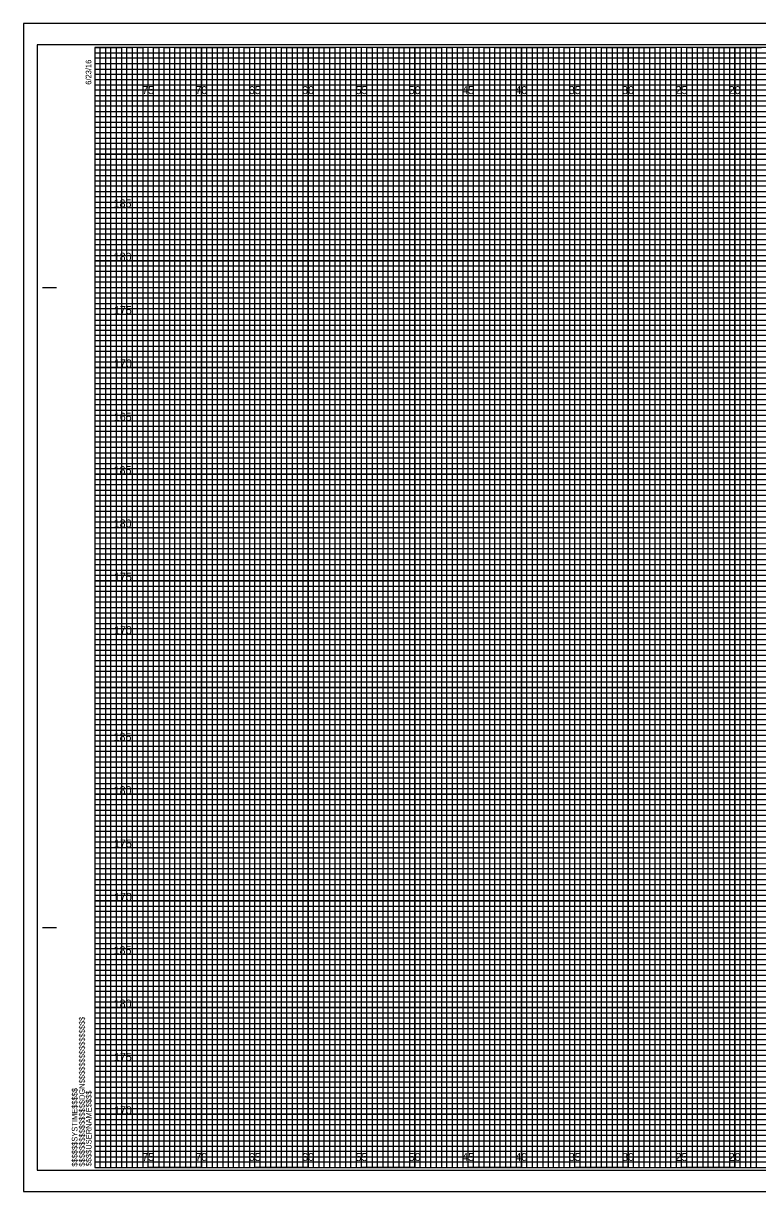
# Model space of a CAD drawing. Extents: x -7 to 162, y -2 to 767.
# Drawn here: x -6.7 to 62.1, y 107.8 to 217.2 of the extents above; entities that cross this region are included whole.
import ezdxf

# ---------------------------------------------------------------- set-up
doc = ezdxf.new("R2010")
doc.units = 0
for name, color, linetype in [('Exist Cross Section Cell', 7, 'Continuous'), ('Prop CMT Pvmt Course 1', 7, 'Continuous'), ('Prop CMT Pvmt Course 1 Wedge', 7, 'Continuous'), ('Prop CMT Pvmt Course 2', 7, 'Continuous'), ('Prop CMT Pvmt Course 3', 7, 'Continuous'), ('Prop CMT Pvmt Surface Shoulder', 7, 'Continuous'), ('Prop CMT Shld Paved Course 2', 7, 'Continuous'), ('Prop CMT Shld Paved Course 3', 7, 'Continuous'), ('Prop CMT Slope Grass', 7, 'Continuous'), ('Prop CMT Subgrade Earthwork', 7, 'Continuous'), ('Scratch_Level_0', 7, 'Continuous')]:
    doc.layers.add(name, color=color, linetype=linetype)

msp = doc.modelspace()

# ---------------------------------------------------------------- linework, layer by layer
at = {"layer": 'Prop CMT Pvmt Course 1'}
for p, q in [((0, 214.5), (130, 214.5)), ((130, 213.99), (0, 213.99)), ((0, 213.99), (0, 213.5)), ((0, 213.5), (130, 213.5)), ((130, 212.94), (0, 212.94)), ((0, 212.94), (0, 212)), ((0, 212), (160, 212))]:
    msp.add_line(p, q, dxfattribs=at)
for points in [[(0, 211.5), (135, 211.5), (160, 211.5), (160, 211), (0, 211)], [(0, 210.5), (160, 210.5), (160, 209.5), (0, 209.5)], [(0, 209), (160, 209), (160, 208.5), (0, 208.49)], [(0, 208), (160, 208), (160, 207), (0, 207)], [(0, 206.5), (160, 206.5), (160, 206), (0, 206)], [(0, 205.5), (160, 205.5), (160, 204.5), (0, 204.5)], [(0, 204), (160, 204), (160, 203.5), (0, 203.5)], [(0, 203), (160, 203), (160, 202), (0, 202)], [(0, 201.5), (160, 201.5), (160, 201), (0, 201)], [(0, 200.5), (160, 200.5), (160, 199.5), (0, 199.5)], [(0, 199), (160, 199), (160, 198.5), (0, 198.5)], [(0, 198), (160, 198), (160, 196.97), (160, 196.5), (160, 196), (0, 196)], [(0, 197), (160, 197), (160, 196.5), (0, 196.5)], [(0, 195.5), (160, 195.5), (160, 194.5), (0, 194.52)], [(0, 194.52), (160, 194.5), (160, 194), (0, 194)], [(0, 193.5), (160, 193.5), (160, 193), (0, 193)], [(0, 192), (160, 192), (160, 191.5), (0, 191.5)], [(0, 191), (160, 191), (160, 190.5), (0, 190.5)], [(-0.04, 189.44), (160, 189.44), (160, 188.94), (-0.04, 188.94)], [(0, 188.5), (160, 188.5), (160, 188), (0, 188)], [(0, 187), (160, 187), (160, 186.5), (0, 186.5)], [(0, 186), (160, 186), (160, 185.5), (0, 185.5)], [(0, 184.5), (160, 184.5), (160, 184), (0, 184)], [(0, 183.5), (160, 183.5), (160, 183), (0, 183)], [(0, 182), (160, 182), (160, 181.5), (0, 181.5)], [(0, 181), (160, 181), (160, 180.5), (0, 180.5)], [(0, 179.5), (160, 179.5), (160, 178.99), (0, 179)], [(0, 178.5), (160, 178.5), (160, 178), (0, 178)], [(0, 177), (160, 177), (160, 176.5), (0, 176.5)], [(0, 176), (160, 176), (160, 175.5), (0, 175.5)], [(0, 174.5), (160, 174.5), (160, 174), (0, 174)], [(0, 173.5), (160, 173.5), (160, 173), (0, 173)], [(0, 172), (160, 172), (160, 171.5), (0, 171.5)], [(0, 171), (160, 171), (160, 170.5), (0, 170.5)], [(0, 169.5), (160, 169.5), (160, 169), (0, 169)], [(0, 168.5), (160.03, 168.46), (160, 168), (0, 168)], [(0, 167), (160, 167), (160, 166.5), (0, 166.5)], [(0, 166), (160, 166), (160, 165.5), (0, 165.5)], [(0, 164.5), (160, 164.5), (160, 164), (0, 164)], [(0, 163.5), (160, 163.5), (160, 163), (0, 163)], [(0, 162), (160, 162), (160, 161.5), (0, 161.5)], [(0, 161), (160, 161), (160, 160.5), (0, 160.5)], [(0, 159.5), (160, 159.5), (160, 159), (0, 159)], [(0, 158.5), (160, 158.5), (160, 158), (0, 158)], [(0, 157), (160, 157), (160, 156.5), (0, 156.5)], [(0, 156), (160, 156), (160, 155.5), (0, 155.5)], [(0, 154.5), (160, 154.5), (160, 154), (0, 154)], [(0, 153.5), (160, 153.5), (160, 153), (0, 153)], [(0, 152), (160, 152), (160, 151.5), (0, 151.5)], [(0, 151), (160, 151), (160, 150.5), (0, 150.5)], [(0, 149.5), (160, 149.5), (160, 148.99), (0, 149)], [(0, 148.5), (160, 148.5), (160, 148), (0, 148)], [(0, 147), (160, 147), (160, 146.5), (0, 146.5)], [(0, 146), (160, 146), (160, 145.5), (0, 145.5)], [(0, 144.5), (160, 144.5), (160, 144), (0, 144)], [(0, 143.5), (160, 143.5), (160, 143), (0, 143)], [(0, 142), (160, 142), (160, 141.5), (0, 141.5)], [(0, 141), (160, 141), (160, 140.5), (0, 140.5)], [(0, 139.5), (160, 139.5), (160, 139), (0, 139)], [(0, 138.5), (160.03, 138.46), (160, 138), (0, 138)], [(0, 137), (160, 137), (160, 136.5), (0, 136.5)], [(0, 136), (160, 136), (160, 135.5), (0, 135.5)], [(0, 134.5), (160, 134.5), (160, 134), (0, 134)], [(0, 133.5), (160, 133.5), (160, 133), (0, 133)], [(0, 132), (160, 132), (160, 131.5), (0, 131.5)], [(0, 131), (160, 131), (160, 130.5), (0, 130.5)], [(0, 129.5), (160, 129.5), (160, 129), (0, 129)], [(0, 128.5), (160, 128.5), (160, 128), (0, 128)], [(0, 127), (160, 127), (160, 126.5), (0, 126.5)], [(0, 126), (160, 126), (160, 125.5), (0, 125.5)], [(0, 124.5), (160, 124.5), (160, 124), (0, 124)], [(0, 123.5), (160, 123.5), (160, 123), (0, 123)], [(0, 122), (160, 122), (160, 121.5), (0, 121.5)], [(0, 121), (160, 121), (160, 120.5), (0, 120.5)], [(0, 119.5), (160, 119.5), (160, 119), (0, 119)], [(0, 118.5), (160, 118.5), (160, 118), (0, 118)], [(0, 117), (160, 117), (160, 116.5), (0, 116.5)], [(0, 116), (160, 116), (160, 115.5), (0, 115.5)], [(0, 114.5), (160, 114.5), (160, 114), (0, 114)], [(0, 113.5), (160, 113.5), (160, 113), (0, 113)], [(0, 112), (160, 112), (160, 111.5), (0, 111.5)], [(0, 111), (160, 111), (160, 110.5), (0, 110.5)]]:
    msp.add_lwpolyline(points, dxfattribs=at)
at = {"layer": 'Prop CMT Pvmt Course 2'}
for p, q in [((5, 110), (5, 215)), ((10, 110), (10, 215)), ((15, 110), (15, 215)), ((20, 110), (20, 215)), ((25, 110), (25, 215)), ((30, 110), (30, 215)), ((35, 110), (35, 215)), ((40, 110), (40, 215)), ((45, 110), (45, 215)), ((50, 110), (50, 215)), ((55, 110), (55, 215)), ((60, 110), (60, 215)), ((0, 210), (160, 210)), ((0, 205), (160, 205)), ((0, 200), (160, 200)), ((0, 195), (160, 195)), ((0, 190), (160, 190)), ((0, 185), (160, 185)), ((0, 180), (160, 180)), ((0, 175), (160, 175)), ((0, 170), (160, 170)), ((0, 165), (160, 165)), ((0, 160), (160, 160)), ((0, 155), (160, 155)), ((0, 150), (160, 150)), ((0, 145), (160, 145)), ((0, 140), (160, 140)), ((0, 135), (160, 135)), ((0, 130), (160, 130)), ((0, 125), (160, 125)), ((0, 120), (160, 120)), ((0, 115), (160, 115))]:
    msp.add_line(p, q, dxfattribs=at)
at = {"layer": 'Prop CMT Pvmt Course 3'}
for p, q in [((161.65, 217.25), (-6.7, 217.25)), ((-6.7, 217.25), (-6.7, 107.75)), ((-6.7, 107.75), (161.65, 107.75))]:
    msp.add_line(p, q, dxfattribs=at)
at = {"layer": 'Prop CMT Pvmt Surface Shoulder'}
for points in [[(0, 215), (2.5, 215), (2.5, 110), (7.5, 110), (7.5, 215), (12.5, 215), (12.5, 110), (17.5, 110), (17.5, 215), (22.5, 215), (22.5, 110), (27.5, 110), (27.5, 215), (32.5, 215), (32.5, 110), (37.5, 110), (37.5, 215), (42.5, 215), (42.5, 110), (47.5, 110), (47.5, 215), (52.5, 215), (52.5, 110), (57.5, 110), (57.5, 215), (62.5, 215)], [(0, 212.5), (137.5, 212.5)], [(0, 202.5), (160, 202.5), (160, 207.5), (0, 207.5)], [(0, 192.5), (160, 192.5), (160, 197.5), (0, 197.5)], [(0, 182.5), (160, 182.5), (160, 187.5), (0, 187.5)], [(0, 172.5), (160, 172.5), (160, 177.5), (0, 177.5)], [(0, 162.5), (160, 162.5), (160, 167.5), (0, 167.5)], [(0, 152.5), (160, 152.5), (160, 157.5), (0, 157.5)], [(0, 142.5), (160, 142.5), (160, 147.5), (0, 147.5)], [(0, 132.5), (160, 132.5), (160, 137.5), (0, 137.5)], [(0, 122.5), (160, 122.5), (160, 127.5), (0, 127.5)], [(0, 112.5), (160, 112.5), (160, 117.5), (0, 117.5)]]:
    msp.add_lwpolyline(points, dxfattribs=at)
at = {"layer": 'Prop CMT Shld Paved Course 2'}
msp.add_lwpolyline([(-6.7, 107.75), (161.65, 107.75), (161.65, 217.25), (-6.7, 217.25)], close=True, dxfattribs=at)
at = {"layer": 'Prop CMT Shld Paved Course 3'}
msp.add_lwpolyline([(-5.4, 109.75), (161.2, 109.75), (161.2, 215.25), (-5.4, 215.25)], close=True, dxfattribs=at)
at = {"layer": 'Prop CMT Slope Grass'}
for points in [[(0, 110), (0.5, 110), (0.5, 215), (1, 215), (1, 110)], [(1, 110), (1.5, 110), (1.5, 215), (2, 215), (2, 110)], [(2.5, 110), (3, 110), (3, 215), (3.5, 215), (3.5, 110)], [(3.5, 110), (4, 110), (4, 215), (4.5, 215), (4.5, 110)], [(5, 110), (5.5, 110), (5.5, 215), (6, 215), (6, 110)], [(6, 110), (6.5, 110), (6.5, 215), (7, 215), (7, 110)], [(7.5, 110), (8, 110), (8, 215), (8.5, 215), (8.5, 110)], [(8.5, 110), (9, 110), (9, 215), (9.5, 215), (9.5, 110)], [(10, 110), (10.5, 110), (10.5, 215), (11, 215), (11, 110)], [(11, 110), (11.5, 110), (11.5, 215), (12, 215), (12, 110)], [(12.5, 110), (13, 110), (13, 215), (13.5, 215), (13.5, 110)], [(13.5, 110), (14, 110), (14, 215), (14.5, 215), (14.5, 110)], [(15, 110), (15.5, 110), (15.5, 215), (16, 215), (16, 110)], [(16, 110), (16.5, 110), (16.5, 215), (17, 215), (17, 110)], [(17.5, 110), (18, 110), (18, 215), (18.5, 215), (18.5, 110)], [(18.5, 110), (19, 110), (19, 215), (19.5, 215), (19.5, 110)], [(20, 110), (20.5, 110), (20.5, 215), (21, 215), (21, 110)], [(21, 110), (21.5, 110), (21.5, 215), (22, 215), (22, 110)], [(22.5, 110), (23, 110), (23, 215), (23.5, 215), (23.5, 110)], [(23.5, 110), (24, 110), (24, 215), (24.5, 215), (24.5, 110)], [(25, 110), (25.5, 110), (25.5, 215), (26, 215), (26, 110)], [(26, 110), (26.5, 110), (26.5, 215), (27, 215), (27, 110)], [(27.5, 110), (28, 110), (28, 215), (28.5, 215), (28.5, 110)], [(28.5, 110), (29, 110), (29, 215), (29.5, 215), (29.5, 110)], [(30, 110), (30.5, 110), (30.5, 215), (31, 215), (31, 110)], [(31, 110), (31.5, 110), (31.5, 215), (32, 215), (32, 110)], [(32.5, 110), (33, 110), (33, 215), (33.5, 215), (33.5, 110)], [(33.5, 110), (34, 110), (34, 215), (34.5, 215), (34.5, 110)], [(35, 110), (35.5, 110), (35.5, 215), (36, 215), (36, 110)], [(36, 110), (36.5, 110), (36.5, 215), (37, 215), (37, 110)], [(37.5, 110), (38, 110), (38, 215), (38.5, 215), (38.5, 110)], [(38.5, 110), (39, 110), (39, 215), (39.5, 215), (39.5, 110)], [(40, 110), (40.5, 110), (40.5, 215), (41, 215), (41, 110)], [(41, 110), (41.5, 110), (41.5, 215), (42, 215), (42, 110)], [(42.5, 110), (43, 110), (43, 215), (43.5, 215), (43.5, 110)], [(43.5, 110), (44, 110), (44, 215), (44.5, 215), (44.5, 110)], [(45, 110), (45.5, 110), (45.5, 215), (46, 215), (46, 110)], [(46, 110), (46.5, 110), (46.5, 215), (47, 215), (47, 110)], [(47.5, 110), (48, 110), (48, 215), (48.5, 215), (48.5, 110)], [(48.5, 110), (49, 110), (49, 215), (49.5, 215), (49.5, 110)], [(50, 110), (50.5, 110), (50.5, 215), (51, 215), (51, 110)], [(51, 110), (51.5, 110), (51.5, 215), (52, 215), (52, 110)], [(52.5, 110), (53, 110), (53, 215), (53.5, 215), (53.5, 110)], [(53.5, 110), (54, 110), (54, 215), (54.5, 215), (54.5, 110)], [(55, 110), (55.5, 110), (55.5, 215), (56, 215), (56, 110)], [(56, 110), (56.5, 110), (56.5, 215), (57, 215), (57, 110)], [(57.5, 110), (58, 110), (58, 215), (58.5, 215), (58.5, 110)], [(58.5, 110), (59, 110), (59, 215), (59.5, 215), (59.5, 110)], [(60, 110), (60.5, 110), (60.5, 215), (61, 215), (61, 110)], [(61, 110), (61.5, 110), (61.5, 215), (62, 215), (62, 110)]]:
    msp.add_lwpolyline(points, dxfattribs=at)
at = {"layer": 'Prop CMT Subgrade Earthwork'}
for p, q in [((-4.9, 192.5), (-3.65, 192.5)), ((-4.85, 192.5), (-3.6, 192.5)), ((-4.9, 132.5), (-3.65, 132.5)), ((-4.85, 132.5), (-3.6, 132.5)), ((0, 110), (0, 110)), ((0, 110), (0, 110)), ((0, 110), (0, 110)), ((0, 110), (0, 110)), ((0, 110), (0, 110)), ((0, 110), (0, 110)), ((0, 110), (0, 110))]:
    msp.add_line(p, q, dxfattribs=at)
msp.add_lwpolyline([(160, 215), (0, 215), (0, 110), (160, 110)], close=True, dxfattribs=at)
at = {"layer": 'Scratch_Level_0'}
for p, q in [((5, 215), (0, 215)), ((5, 110), (5, 215)), ((15, 215), (10, 215)), ((10, 215), (10, 110)), ((15, 110), (15, 215)), ((25, 215), (20, 215)), ((20, 215), (20, 110)), ((25, 110), (25, 215)), ((35, 215), (30, 215)), ((30, 215), (30, 110)), ((35, 110), (35, 215)), ((45, 215), (40, 215)), ((40, 215), (40, 110)), ((45, 110), (45, 215)), ((55, 215), (50, 215)), ((50, 215), (50, 110)), ((55, 110), (55, 215)), ((65, 215), (60, 215)), ((60, 215), (60, 110)), ((10, 110), (5, 110)), ((20, 110), (15, 110)), ((30, 110), (25, 110)), ((40, 110), (35, 110)), ((50, 110), (45, 110)), ((60, 110), (55, 110))]:
    msp.add_line(p, q, dxfattribs=at)
for points in [[(0, 210), (160, 210), (160, 205), (0, 205)], [(0, 200), (160, 200), (160, 195), (0, 195)], [(0, 190), (160, 190), (160, 185), (0, 185)], [(0, 180), (160, 180), (160, 175), (0, 175)], [(0, 170), (160, 170), (160, 165), (0, 165)], [(0, 160), (160, 160), (160, 155), (0, 155)], [(0, 150), (160, 150), (160, 145), (0, 145)], [(0, 140), (160, 140), (160, 135), (0, 135)], [(0, 130), (160, 130), (160, 125), (0, 125)], [(0, 120), (160, 120), (160, 115), (0, 115)]]:
    msp.add_lwpolyline(points, dxfattribs=at)

# ---------------------------------------------------------------- texts
at = {"layer": 'Exist Cross Section Cell'}
for s, p in [('75', (4.44, 210.62)), ('70', (9.43, 210.62)), ('65', (14.44, 210.62)), ('60', (19.43, 210.62)), ('55', (24.44, 210.62)), ('50', (29.43, 210.62)), ('45', (34.44, 210.62)), ('40', (39.43, 210.62)), ('35', (44.44, 210.62)), ('30', (49.43, 210.62)), ('25', (54.44, 210.62)), ('20', (59.43, 210.62)), ('75', (4.44, 110.62)), ('70', (9.43, 110.62)), ('65', (14.44, 110.62)), ('60', (19.43, 110.62)), ('55', (24.44, 110.62)), ('50', (29.43, 110.62)), ('45', (34.44, 110.62)), ('40', (39.43, 110.62)), ('35', (44.44, 110.62)), ('30', (49.43, 110.62)), ('25', (54.44, 110.62)), ('20', (59.43, 110.62))]:
    msp.add_text(s, height=0.75, dxfattribs=at).set_placement(p)
at = {"layer": 'Prop CMT Pvmt Course 1 Wedge'}
for s, p in [('185', (1.76, 200)), ('180', (1.77, 195)), ('175', (1.79, 190)), ('170', (1.8, 185)), ('165', (1.78, 180)), ('185', (1.76, 175)), ('180', (1.77, 170)), ('175', (1.79, 165)), ('170', (1.8, 160)), ('185', (1.76, 150)), ('180', (1.77, 145)), ('175', (1.79, 140)), ('170', (1.8, 135)), ('185', (1.76, 130)), ('180', (1.77, 125)), ('175', (1.79, 120)), ('170', (1.8, 115))]:
    msp.add_text(s, height=0.75, dxfattribs=at).set_placement(p)
at = {"layer": 'Prop CMT Subgrade Earthwork'}
for s, p in [('6/23/16', (-0.33, 211.5)), ('$$$$$$$$$$$$$$$$DGN$$$$$$$$$$$$$$$$', (-0.94, 110.09)), ('$$$$$$SYSTIME$$$$$', (-1.63, 110.09)), ('$$$$USERNAME$$$$', (-0.31, 110.12))]:
    msp.add_text(s, height=0.525, rotation=90, dxfattribs=at).set_placement(p)

doc.saveas('drawing.dxf')
